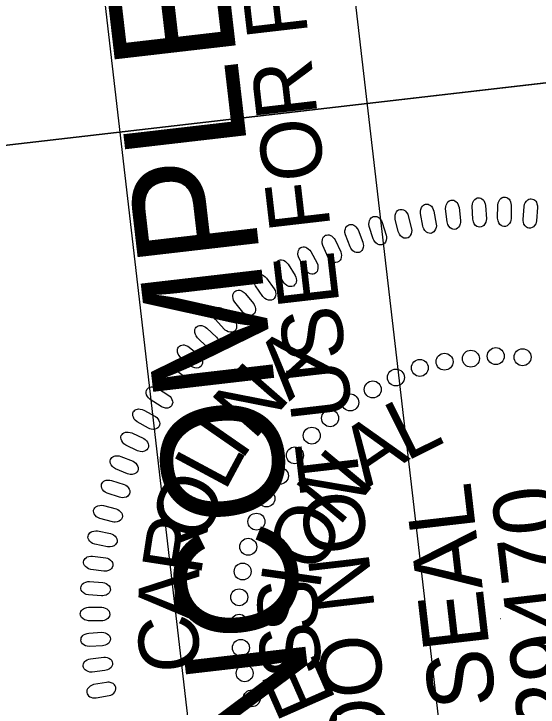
# Model space of a CAD drawing. Extents: x 477709 to 478991, y 494339 to 496137.
# Drawn here: x 477804.8 to 477854.4, y 495851.4 to 495917.1 of the extents above; entities that cross this region are included whole.
import ezdxf

# ---------------------------------------------------------------- set-up
doc = ezdxf.new("R2010")
doc.units = 0
for name, color, linetype in [('Sheet PE Seal Cell', 7, 'Continuous'), ('Sheet Plan CELL', 7, 'Continuous'), ('Sheet Sticker Incomplete CELL', 7, 'Continuous')]:
    doc.layers.add(name, color=color, linetype=linetype)

msp = doc.modelspace()

# ---------------------------------------------------------------- linework, layer by layer
at = {"layer": 'Sheet PE Seal Cell'}
msp.add_line((477850.756, 495859.818), (477850.803, 495859.823), dxfattribs=at)
for points in [[(477845.751, 495897.373), (477845.61, 495898.592), (477845.622, 495898.814), (477845.658, 495898.959), (477845.75, 495899.14), (477845.833, 495899.26), (477845.936, 495899.352), (477846.035, 495899.403), (477846.145, 495899.436), (477846.258, 495899.429), (477846.38, 495899.413), (477846.491, 495899.366), (477846.607, 495899.279), (477846.675, 495899.206), (477846.759, 495899.065), (477846.839, 495898.894), (477846.88, 495898.739), (477847.032, 495897.491), (477847.029, 495897.32), (477847, 495897.176), (477846.929, 495897.007), (477846.834, 495896.856), (477846.747, 495896.765), (477846.597, 495896.687), (477846.451, 495896.651), (477846.298, 495896.673), (477846.189, 495896.711), (477846.05, 495896.795), (477845.913, 495896.95), (477845.825, 495897.121), (477845.78, 495897.246)], [(477848.179, 495897.621), (477848.115, 495898.846), (477848.141, 495899.066), (477848.186, 495899.209), (477848.289, 495899.385), (477848.38, 495899.499), (477848.488, 495899.584), (477848.59, 495899.63), (477848.702, 495899.655), (477848.814, 495899.641), (477848.935, 495899.618), (477849.043, 495899.564), (477849.152, 495899.469), (477849.216, 495899.393), (477849.292, 495899.247), (477849.361, 495899.07), (477849.391, 495898.912), (477849.464, 495897.658), (477849.451, 495897.488), (477849.413, 495897.346), (477849.332, 495897.182), (477849.227, 495897.037), (477849.134, 495896.951), (477848.981, 495896.884), (477848.832, 495896.856), (477848.681, 495896.888), (477848.574, 495896.933), (477848.442, 495897.025), (477848.314, 495897.188), (477848.237, 495897.365), (477848.201, 495897.492)], [(477850.522, 495897.724), (477850.536, 495898.952), (477850.575, 495899.17), (477850.629, 495899.309), (477850.743, 495899.479), (477850.841, 495899.587), (477850.954, 495899.665), (477851.059, 495899.704), (477851.172, 495899.722), (477851.283, 495899.701), (477851.403, 495899.67), (477851.507, 495899.609), (477851.61, 495899.509), (477851.669, 495899.428), (477851.735, 495899.278), (477851.792, 495899.098), (477851.813, 495898.938), (477851.807, 495897.681), (477851.783, 495897.511), (477851.737, 495897.373), (477851.645, 495897.214), (477851.532, 495897.076), (477851.434, 495896.997), (477851.276, 495896.939), (477851.127, 495896.921), (477850.977, 495896.962), (477850.873, 495897.013), (477850.747, 495897.114), (477850.63, 495897.285), (477850.564, 495897.465), (477850.536, 495897.595)], [(477852.939, 495897.605), (477853.03, 495898.828), (477853.083, 495899.044), (477853.144, 495899.18), (477853.269, 495899.341), (477853.375, 495899.443), (477853.492, 495899.515), (477853.599, 495899.546), (477853.713, 495899.558), (477853.823, 495899.53), (477853.94, 495899.491), (477854.04, 495899.424), (477854.137, 495899.316), (477854.191, 495899.233), (477854.247, 495899.079), (477854.293, 495898.895), (477854.304, 495898.735), (477854.219, 495897.481), (477854.184, 495897.313), (477854.129, 495897.178), (477854.028, 495897.025), (477853.906, 495896.894), (477853.804, 495896.821), (477853.642, 495896.773), (477853.492, 495896.765), (477853.346, 495896.815), (477853.245, 495896.873), (477853.125, 495896.981), (477853.019, 495897.159), (477852.965, 495897.344), (477852.945, 495897.475)], [(477843.453, 495896.957), (477843.236, 495898.164), (477843.235, 495898.386), (477843.26, 495898.533), (477843.341, 495898.72), (477843.417, 495898.845), (477843.514, 495898.943), (477843.61, 495899.001), (477843.717, 495899.04), (477843.83, 495899.041), (477843.953, 495899.033), (477844.067, 495898.992), (477844.188, 495898.913), (477844.26, 495898.844), (477844.354, 495898.709), (477844.444, 495898.543), (477844.494, 495898.39), (477844.724, 495897.154), (477844.732, 495896.984), (477844.712, 495896.838), (477844.652, 495896.665), (477844.566, 495896.508), (477844.485, 495896.412), (477844.341, 495896.326), (477844.197, 495896.28), (477844.043, 495896.293), (477843.931, 495896.323), (477843.788, 495896.399), (477843.641, 495896.544), (477843.543, 495896.709), (477843.491, 495896.832)], [(477841.132, 495896.443), (477840.84, 495897.634), (477840.824, 495897.856), (477840.841, 495898.004), (477840.909, 495898.196), (477840.978, 495898.326), (477841.067, 495898.43), (477841.159, 495898.493), (477841.264, 495898.539), (477841.377, 495898.546), (477841.501, 495898.546), (477841.617, 495898.513), (477841.742, 495898.441), (477841.819, 495898.378), (477841.92, 495898.248), (477842.021, 495898.088), (477842.081, 495897.939), (477842.388, 495896.72), (477842.406, 495896.55), (477842.396, 495896.403), (477842.347, 495896.228), (477842.271, 495896.065), (477842.196, 495895.964), (477842.058, 495895.868), (477841.917, 495895.814), (477841.763, 495895.817), (477841.649, 495895.841), (477841.502, 495895.907), (477841.345, 495896.043), (477841.237, 495896.202), (477841.178, 495896.321)], [(477838.755, 495895.767), (477838.388, 495896.937), (477838.359, 495897.158), (477838.366, 495897.307), (477838.423, 495897.502), (477838.483, 495897.635), (477838.566, 495897.746), (477838.654, 495897.814), (477838.755, 495897.867), (477838.867, 495897.881), (477838.991, 495897.888), (477839.108, 495897.863), (477839.238, 495897.799), (477839.319, 495897.741), (477839.428, 495897.618), (477839.539, 495897.464), (477839.608, 495897.319), (477839.991, 495896.122), (477840.02, 495895.953), (477840.019, 495895.807), (477839.981, 495895.628), (477839.915, 495895.461), (477839.847, 495895.356), (477839.715, 495895.252), (477839.578, 495895.188), (477839.424, 495895.182), (477839.309, 495895.198), (477839.157, 495895.255), (477838.993, 495895.381), (477838.874, 495895.533), (477838.808, 495895.647)], [(477836.574, 495895.001), (477836.135, 495896.146), (477836.091, 495896.364), (477836.09, 495896.513), (477836.134, 495896.712), (477836.185, 495896.849), (477836.261, 495896.964), (477836.345, 495897.038), (477836.442, 495897.097), (477836.554, 495897.119), (477836.677, 495897.134), (477836.795, 495897.116), (477836.929, 495897.06), (477837.014, 495897.007), (477837.13, 495896.891), (477837.25, 495896.745), (477837.328, 495896.604), (477837.785, 495895.434), (477837.825, 495895.267), (477837.833, 495895.121), (477837.807, 495894.939), (477837.752, 495894.769), (477837.69, 495894.66), (477837.565, 495894.548), (477837.432, 495894.476), (477837.278, 495894.46), (477837.163, 495894.468), (477837.008, 495894.516), (477836.836, 495894.631), (477836.709, 495894.775), (477836.635, 495894.885)], [(477834.501, 495894.011), (477833.991, 495895.127), (477833.934, 495895.342), (477833.922, 495895.49), (477833.954, 495895.691), (477833.997, 495895.831), (477834.066, 495895.951), (477834.144, 495896.03), (477834.238, 495896.095), (477834.348, 495896.124), (477834.469, 495896.146), (477834.589, 495896.135), (477834.726, 495896.088), (477834.814, 495896.041), (477834.938, 495895.932), (477835.066, 495895.794), (477835.153, 495895.658), (477835.683, 495894.519), (477835.733, 495894.356), (477835.75, 495894.21), (477835.735, 495894.028), (477835.691, 495893.854), (477835.636, 495893.741), (477835.518, 495893.62), (477835.39, 495893.541), (477835.238, 495893.515), (477835.122, 495893.517), (477834.965, 495893.554), (477834.786, 495893.658), (477834.649, 495893.794), (477834.569, 495893.899)], [(477832.303, 495892.876), (477831.723, 495893.958), (477831.653, 495894.169), (477831.633, 495894.316), (477831.651, 495894.518), (477831.686, 495894.661), (477831.747, 495894.784), (477831.82, 495894.869), (477831.909, 495894.94), (477832.018, 495894.975), (477832.137, 495895.005), (477832.257, 495895.002), (477832.397, 495894.963), (477832.487, 495894.922), (477832.618, 495894.821), (477832.755, 495894.691), (477832.85, 495894.561), (477833.45, 495893.457), (477833.511, 495893.297), (477833.537, 495893.153), (477833.533, 495892.97), (477833.501, 495892.794), (477833.452, 495892.677), (477833.342, 495892.551), (477833.22, 495892.463), (477833.069, 495892.427), (477832.953, 495892.422), (477832.794, 495892.449), (477832.609, 495892.543), (477832.465, 495892.669), (477832.377, 495892.769)], [(477830.269, 495891.655), (477829.622, 495892.697), (477829.539, 495892.903), (477829.509, 495893.049), (477829.516, 495893.253), (477829.541, 495893.397), (477829.594, 495893.525), (477829.662, 495893.613), (477829.747, 495893.69), (477829.852, 495893.731), (477829.97, 495893.769), (477830.09, 495893.774), (477830.232, 495893.744), (477830.325, 495893.707), (477830.461, 495893.615), (477830.606, 495893.494), (477830.709, 495893.37), (477831.377, 495892.306), (477831.447, 495892.15), (477831.483, 495892.008), (477831.491, 495891.826), (477831.469, 495891.648), (477831.429, 495891.529), (477831.326, 495891.395), (477831.21, 495891.299), (477831.062, 495891.254), (477830.946, 495891.242), (477830.786, 495891.259), (477830.595, 495891.341), (477830.443, 495891.458), (477830.35, 495891.553)], [(477828.327, 495890.315), (477827.617, 495891.315), (477827.52, 495891.516), (477827.481, 495891.659), (477827.474, 495891.863), (477827.49, 495892.008), (477827.536, 495892.138), (477827.599, 495892.232), (477827.678, 495892.313), (477827.781, 495892.361), (477827.896, 495892.406), (477828.015, 495892.418), (477828.159, 495892.398), (477828.254, 495892.367), (477828.395, 495892.284), (477828.548, 495892.172), (477828.659, 495892.055), (477829.392, 495891.035), (477829.472, 495890.884), (477829.517, 495890.744), (477829.535, 495890.562), (477829.525, 495890.384), (477829.493, 495890.262), (477829.399, 495890.122), (477829.289, 495890.019), (477829.144, 495889.965), (477829.03, 495889.945), (477828.868, 495889.953), (477828.672, 495890.022), (477828.513, 495890.13), (477828.414, 495890.218)], [(477826.436, 495888.826), (477825.664, 495889.78), (477825.555, 495889.974), (477825.507, 495890.115), (477825.488, 495890.318), (477825.495, 495890.464), (477825.531, 495890.597), (477825.588, 495890.694), (477825.662, 495890.78), (477825.762, 495890.835), (477825.874, 495890.887), (477825.993, 495890.906), (477826.137, 495890.894), (477826.234, 495890.87), (477826.381, 495890.796), (477826.54, 495890.694), (477826.657, 495890.584), (477827.454, 495889.613), (477827.543, 495889.466), (477827.596, 495889.33), (477827.627, 495889.149), (477827.627, 495888.97), (477827.602, 495888.847), (477827.518, 495888.701), (477827.414, 495888.592), (477827.273, 495888.529), (477827.16, 495888.502), (477826.998, 495888.499), (477826.799, 495888.556), (477826.633, 495888.653), (477826.529, 495888.735)], [(477824.664, 495887.211), (477823.834, 495888.115), (477823.713, 495888.301), (477823.657, 495888.439), (477823.624, 495888.64), (477823.622, 495888.787), (477823.65, 495888.921), (477823.701, 495889.021), (477823.77, 495889.112), (477823.866, 495889.173), (477823.974, 495889.232), (477824.091, 495889.259), (477824.236, 495889.256), (477824.334, 495889.238), (477824.485, 495889.173), (477824.65, 495889.082), (477824.775, 495888.98), (477825.631, 495888.059), (477825.729, 495887.92), (477825.791, 495887.786), (477825.832, 495887.608), (477825.844, 495887.429), (477825.827, 495887.305), (477825.752, 495887.155), (477825.655, 495887.038), (477825.518, 495886.967), (477825.407, 495886.933), (477825.246, 495886.92), (477825.044, 495886.964), (477824.872, 495887.051), (477824.762, 495887.126)], [(477823.022, 495885.551), (477822.136, 495886.4), (477822.004, 495886.579), (477821.939, 495886.714), (477821.895, 495886.912), (477821.883, 495887.058), (477821.903, 495887.194), (477821.947, 495887.297), (477822.01, 495887.392), (477822.102, 495887.459), (477822.206, 495887.525), (477822.322, 495887.559), (477822.466, 495887.565), (477822.565, 495887.553), (477822.72, 495887.498), (477822.89, 495887.417), (477823.021, 495887.323), (477823.933, 495886.458), (477824.04, 495886.325), (477824.11, 495886.195), (477824.162, 495886.021), (477824.186, 495885.843), (477824.176, 495885.717), (477824.111, 495885.562), (477824.021, 495885.441), (477823.889, 495885.361), (477823.781, 495885.32), (477823.621, 495885.297), (477823.416, 495885.328), (477823.24, 495885.404), (477823.125, 495885.472)], [(477821.472, 495883.749), (477820.536, 495884.541), (477820.393, 495884.711), (477820.319, 495884.841), (477820.262, 495885.036), (477820.241, 495885.181), (477820.252, 495885.318), (477820.29, 495885.424), (477820.347, 495885.523), (477820.435, 495885.595), (477820.535, 495885.667), (477820.648, 495885.709), (477820.791, 495885.724), (477820.891, 495885.718), (477821.049, 495885.673), (477821.224, 495885.603), (477821.361, 495885.517), (477822.325, 495884.711), (477822.44, 495884.585), (477822.518, 495884.46), (477822.582, 495884.289), (477822.616, 495884.113), (477822.614, 495883.987), (477822.559, 495883.829), (477822.477, 495883.701), (477822.351, 495883.613), (477822.245, 495883.566), (477822.087, 495883.533), (477821.88, 495883.551), (477821.699, 495883.616), (477821.581, 495883.677)], [(477819.991, 495881.821), (477819.006, 495882.553), (477818.852, 495882.713), (477818.771, 495882.839), (477818.702, 495883.03), (477818.672, 495883.174), (477818.675, 495883.311), (477818.705, 495883.419), (477818.756, 495883.521), (477818.839, 495883.599), (477818.934, 495883.677), (477819.044, 495883.725), (477819.187, 495883.75), (477819.287, 495883.751), (477819.447, 495883.715), (477819.627, 495883.656), (477819.768, 495883.579), (477820.781, 495882.835), (477820.904, 495882.716), (477820.989, 495882.597), (477821.064, 495882.43), (477821.109, 495882.257), (477821.115, 495882.131), (477821.07, 495881.969), (477820.997, 495881.837), (477820.875, 495881.742), (477820.773, 495881.687), (477820.617, 495881.645), (477820.41, 495881.65), (477820.226, 495881.703), (477820.104, 495881.756)], [(477818.691, 495879.887), (477817.662, 495880.555), (477817.499, 495880.706), (477817.41, 495880.826), (477817.328, 495881.013), (477817.289, 495881.154), (477817.284, 495881.291), (477817.307, 495881.4), (477817.352, 495881.506), (477817.429, 495881.589), (477817.52, 495881.673), (477817.627, 495881.728), (477817.768, 495881.761), (477817.867, 495881.768), (477818.029, 495881.742), (477818.212, 495881.695), (477818.358, 495881.628), (477819.416, 495880.949), (477819.546, 495880.838), (477819.639, 495880.724), (477819.724, 495880.562), (477819.78, 495880.392), (477819.794, 495880.267), (477819.759, 495880.102), (477819.693, 495879.966), (477819.579, 495879.863), (477819.48, 495879.802), (477819.327, 495879.75), (477819.12, 495879.742), (477818.932, 495879.784), (477818.808, 495879.829)], [(477817.502, 495877.842), (477816.434, 495878.444), (477816.26, 495878.585), (477816.164, 495878.699), (477816.072, 495878.88), (477816.024, 495879.018), (477816.009, 495879.155), (477816.026, 495879.266), (477816.064, 495879.374), (477816.136, 495879.462), (477816.221, 495879.551), (477816.324, 495879.612), (477816.463, 495879.655), (477816.562, 495879.668), (477816.725, 495879.653), (477816.911, 495879.617), (477817.061, 495879.558), (477818.159, 495878.947), (477818.296, 495878.844), (477818.395, 495878.737), (477818.491, 495878.581), (477818.557, 495878.414), (477818.579, 495878.29), (477818.554, 495878.124), (477818.497, 495877.984), (477818.39, 495877.873), (477818.295, 495877.807), (477818.146, 495877.745), (477817.939, 495877.724), (477817.75, 495877.754), (477817.622, 495877.792)], [(477816.467, 495875.709), (477815.363, 495876.243), (477815.182, 495876.372), (477815.079, 495876.48), (477814.975, 495876.655), (477814.918, 495876.79), (477814.895, 495876.926), (477814.905, 495877.037), (477814.936, 495877.148), (477815.003, 495877.24), (477815.082, 495877.334), (477815.181, 495877.402), (477815.317, 495877.453), (477815.415, 495877.472), (477815.579, 495877.468), (477815.766, 495877.443), (477815.92, 495877.394), (477817.054, 495876.854), (477817.197, 495876.759), (477817.303, 495876.658), (477817.408, 495876.508), (477817.485, 495876.347), (477817.515, 495876.224), (477817.5, 495876.057), (477817.452, 495875.914), (477817.352, 495875.797), (477817.261, 495875.724), (477817.116, 495875.652), (477816.911, 495875.619), (477816.72, 495875.637), (477816.59, 495875.666)], [(477815.527, 495873.528), (477814.391, 495873.992), (477814.203, 495874.11), (477814.093, 495874.211), (477813.979, 495874.379), (477813.914, 495874.51), (477813.882, 495874.644), (477813.885, 495874.756), (477813.909, 495874.867), (477813.97, 495874.964), (477814.043, 495875.063), (477814.137, 495875.137), (477814.269, 495875.197), (477814.366, 495875.222), (477814.529, 495875.228), (477814.718, 495875.215), (477814.875, 495875.176), (477816.041, 495874.707), (477816.189, 495874.622), (477816.302, 495874.528), (477816.415, 495874.385), (477816.502, 495874.228), (477816.54, 495874.108), (477816.536, 495873.94), (477816.498, 495873.794), (477816.404, 495873.671), (477816.318, 495873.593), (477816.178, 495873.513), (477815.976, 495873.466), (477815.784, 495873.472), (477815.652, 495873.493)], [(477814.763, 495871.302), (477813.6, 495871.693), (477813.404, 495871.799), (477813.289, 495871.893), (477813.164, 495872.053), (477813.091, 495872.18), (477813.051, 495872.312), (477813.047, 495872.424), (477813.064, 495872.537), (477813.119, 495872.636), (477813.185, 495872.74), (477813.275, 495872.82), (477813.403, 495872.888), (477813.497, 495872.919), (477813.661, 495872.935), (477813.85, 495872.934), (477814.009, 495872.905), (477815.202, 495872.511), (477815.355, 495872.435), (477815.473, 495872.348), (477815.596, 495872.212), (477815.692, 495872.061), (477815.737, 495871.944), (477815.744, 495871.776), (477815.714, 495871.628), (477815.629, 495871.499), (477815.549, 495871.416), (477815.414, 495871.327), (477815.215, 495871.268), (477815.023, 495871.261), (477814.891, 495871.275)], [(477814.093, 495868.968), (477812.908, 495869.285), (477812.706, 495869.379), (477812.584, 495869.465), (477812.45, 495869.617), (477812.369, 495869.74), (477812.321, 495869.869), (477812.31, 495869.98), (477812.319, 495870.094), (477812.368, 495870.196), (477812.428, 495870.304), (477812.513, 495870.39), (477812.636, 495870.465), (477812.728, 495870.503), (477812.89, 495870.529), (477813.079, 495870.54), (477813.239, 495870.52), (477814.455, 495870.202), (477814.613, 495870.136), (477814.736, 495870.057), (477814.866, 495869.929), (477814.973, 495869.785), (477815.025, 495869.67), (477815.041, 495869.503), (477815.022, 495869.353), (477814.945, 495869.219), (477814.87, 495869.131), (477814.74, 495869.034), (477814.545, 495868.963), (477814.355, 495868.944), (477814.222, 495868.949)], [(477813.626, 495866.615), (477812.423, 495866.858), (477812.215, 495866.938), (477812.089, 495867.017), (477811.945, 495867.16), (477811.857, 495867.277), (477811.8, 495867.403), (477811.782, 495867.513), (477811.785, 495867.627), (477811.827, 495867.733), (477811.88, 495867.845), (477811.959, 495867.936), (477812.077, 495868.018), (477812.167, 495868.061), (477812.327, 495868.097), (477812.515, 495868.12), (477812.676, 495868.111), (477813.909, 495867.869), (477814.071, 495867.814), (477814.199, 495867.742), (477814.338, 495867.623), (477814.452, 495867.485), (477814.511, 495867.374), (477814.539, 495867.208), (477814.529, 495867.058), (477814.46, 495866.919), (477814.391, 495866.827), (477814.268, 495866.722), (477814.078, 495866.638), (477813.889, 495866.608), (477813.756, 495866.604)], [(477813.267, 495864.309), (477812.051, 495864.475), (477811.839, 495864.542), (477811.708, 495864.613), (477811.555, 495864.747), (477811.46, 495864.858), (477811.396, 495864.98), (477811.371, 495865.089), (477811.365, 495865.203), (477811.401, 495865.311), (477811.447, 495865.426), (477811.52, 495865.521), (477811.633, 495865.611), (477811.72, 495865.66), (477811.878, 495865.706), (477812.064, 495865.741), (477812.225, 495865.742), (477813.471, 495865.578), (477813.636, 495865.532), (477813.768, 495865.469), (477813.914, 495865.359), (477814.037, 495865.229), (477814.103, 495865.122), (477814.141, 495864.958), (477814.14, 495864.807), (477814.08, 495864.665), (477814.017, 495864.568), (477813.901, 495864.455), (477813.716, 495864.36), (477813.529, 495864.318), (477813.397, 495864.306)], [(477813.061, 495861.964), (477811.838, 495862.054), (477811.622, 495862.108), (477811.487, 495862.17), (477811.326, 495862.294), (477811.224, 495862.399), (477811.152, 495862.517), (477811.12, 495862.624), (477811.108, 495862.738), (477811.136, 495862.848), (477811.175, 495862.965), (477811.243, 495863.065), (477811.35, 495863.162), (477811.433, 495863.216), (477811.588, 495863.272), (477811.771, 495863.319), (477811.932, 495863.329), (477813.186, 495863.244), (477813.353, 495863.209), (477813.489, 495863.154), (477813.642, 495863.053), (477813.772, 495862.931), (477813.845, 495862.828), (477813.893, 495862.667), (477813.902, 495862.517), (477813.851, 495862.371), (477813.794, 495862.27), (477813.685, 495862.151), (477813.507, 495862.044), (477813.323, 495861.99), (477813.192, 495861.97)], [(477813.046, 495859.607), (477811.819, 495859.621), (477811.6, 495859.66), (477811.461, 495859.714), (477811.293, 495859.828), (477811.184, 495859.926), (477811.106, 495860.039), (477811.067, 495860.144), (477811.048, 495860.256), (477811.07, 495860.369), (477811.1, 495860.487), (477811.161, 495860.591), (477811.263, 495860.695), (477811.343, 495860.754), (477811.493, 495860.82), (477811.673, 495860.877), (477811.833, 495860.898), (477813.09, 495860.893), (477813.259, 495860.868), (477813.398, 495860.822), (477813.557, 495860.731), (477813.695, 495860.617), (477813.774, 495860.519), (477813.832, 495860.361), (477813.85, 495860.212), (477813.809, 495860.063), (477813.758, 495859.959), (477813.657, 495859.832), (477813.486, 495859.714), (477813.305, 495859.649), (477813.175, 495859.621)], [(477813.144, 495857.24), (477811.918, 495857.176), (477811.697, 495857.202), (477811.556, 495857.247), (477811.38, 495857.35), (477811.266, 495857.442), (477811.18, 495857.549), (477811.135, 495857.652), (477811.109, 495857.763), (477811.124, 495857.876), (477811.147, 495857.997), (477811.201, 495858.105), (477811.295, 495858.214), (477811.372, 495858.278), (477811.518, 495858.353), (477811.694, 495858.422), (477811.852, 495858.453), (477813.107, 495858.526), (477813.277, 495858.513), (477813.419, 495858.475), (477813.583, 495858.393), (477813.728, 495858.289), (477813.813, 495858.196), (477813.881, 495858.042), (477813.909, 495857.894), (477813.877, 495857.743), (477813.832, 495857.635), (477813.739, 495857.503), (477813.576, 495857.376), (477813.4, 495857.299), (477813.272, 495857.262)], [(477813.389, 495854.894), (477812.17, 495854.753), (477811.948, 495854.765), (477811.803, 495854.801), (477811.622, 495854.893), (477811.502, 495854.977), (477811.41, 495855.079), (477811.358, 495855.178), (477811.325, 495855.288), (477811.332, 495855.401), (477811.348, 495855.524), (477811.396, 495855.634), (477811.483, 495855.75), (477811.556, 495855.818), (477811.696, 495855.902), (477811.868, 495855.983), (477812.024, 495856.023), (477813.271, 495856.174), (477813.442, 495856.172), (477813.586, 495856.143), (477813.754, 495856.072), (477813.907, 495855.977), (477813.997, 495855.89), (477814.074, 495855.74), (477814.111, 495855.594), (477814.089, 495855.442), (477814.051, 495855.332), (477813.967, 495855.194), (477813.812, 495855.056), (477813.641, 495854.968), (477813.516, 495854.924)], [(477813.526, 495853.787), (477812.319, 495853.57), (477812.109, 495853.494), (477811.982, 495853.418), (477811.834, 495853.278), (477811.743, 495853.163), (477811.685, 495853.038), (477811.664, 495852.929), (477811.664, 495852.814), (477811.704, 495852.708), (477811.754, 495852.595), (477811.831, 495852.502), (477811.948, 495852.417), (477812.037, 495852.373), (477812.197, 495852.333), (477812.384, 495852.305), (477812.545, 495852.312), (477813.783, 495852.527), (477813.946, 495852.579), (477814.075, 495852.648), (477814.217, 495852.764), (477814.334, 495852.9), (477814.396, 495853.009), (477814.427, 495853.174), (477814.42, 495853.325), (477814.354, 495853.465), (477814.286, 495853.559), (477814.165, 495853.666), (477813.978, 495853.754), (477813.789, 495853.788), (477813.656, 495853.795)]]:
    msp.add_lwpolyline(points, close=True, dxfattribs=at)
for centre in [(477848.003, 495884.423), (477850.354, 495884.666), (477852.893, 495884.558), (477843.172, 495883.545), (477845.51, 495884.135), (477840.91, 495882.642), (477838.715, 495881.507), (477836.593, 495880.282), (477834.681, 495878.779), (477832.946, 495877.136), (477831.357, 495875.269), (477829.935, 495873.341), (477828.66, 495871.19), (477827.71, 495868.996), (477826.942, 495866.623), (477826.411, 495864.277), (477826.091, 495861.836), (477826.088, 495859.431), (477826.244, 495857.044), (477826.601, 495854.641), (477827.276, 495852.274)]:
    msp.add_circle(centre, 0.801, dxfattribs=at)
at = {"layer": 'Sheet Plan CELL'}
msp.add_line((477782.292, 495902.094), (477894.006, 495915.047), dxfattribs=at)
for points in [[(477782.292, 495902.094), (477770.774, 496001.416), (477882.538, 496014.375), (477894.057, 495915.04)], [(477793.804, 495802.709), (477782.292, 495902.094), (477894.057, 495915.04), (477905.543, 495815.665)]]:
    msp.add_lwpolyline(points, close=True, dxfattribs=at)
at = {"layer": 'Sheet Sticker Incomplete CELL'}
msp.add_lwpolyline([(477846.625, 495835.555), (477823.281, 495832.851), (477806.367, 495978.874), (477829.711, 495981.578)], close=True, dxfattribs=at)

# ---------------------------------------------------------------- texts
at = {"layer": 'Sheet PE Seal Cell'}
for s, height, rotation, p in [('A', 5.669, 42.28018, (477830.824, 495880.332)), ('N', 5.669, 48.76954, (477827.451, 495876.599)), ('L', 5.669, 26.43822, (477841.882, 495874.674)), ('I', 5.669, 55.2589, (477826.248, 495874.642)), ('A', 5.669, 34.37801, (477838.158, 495872.105)), ('N', 5.669, 50.25761, (477835.482, 495868.436)), ('L', 5.669, 61.74825, (477824.717, 495871.754)), ('O', 5.669, 68.23761, (477822.748, 495866.761)), ('SEAL', 6.2363, 96.58872, (477850.397, 495851.68)), ('29470', 6.2363, 96.58872, (477858.763, 495849.658)), ('O', 5.669, 66.1372, (477833.689, 495863.887)), ('R', 5.669, 81.21632, (477822.438, 495863.75)), ('A', 5.669, 87.70568, (477822.133, 495859.481)), ('I', 5.669, 82.0168, (477833.692, 495862.374)), ('S', 5.669, 89.95659, (477833.502, 495858.526)), ('C', 5.669, 94.19504, (477822.452, 495854.912)), ('S', 5.669, 97.89639, (477834.046, 495854.703)), ('E', 5.669, 113.77599, (477835.318, 495852.064))]:
    msp.add_text(s, height=height, rotation=rotation, dxfattribs=at).set_placement(p)
at = {"layer": 'Sheet Sticker Incomplete CELL'}
for s, height, p in [('INCOMPLETE PLANS', 11.52, (477833.973, 495843.099)), ('DO NOT USE FOR R/W ACQUISITION', 5.76, (477840.503, 495847.127))]:
    msp.add_text(s, height=height, rotation=96.60736, dxfattribs=at).set_placement(p)

doc.saveas('drawing.dxf')
